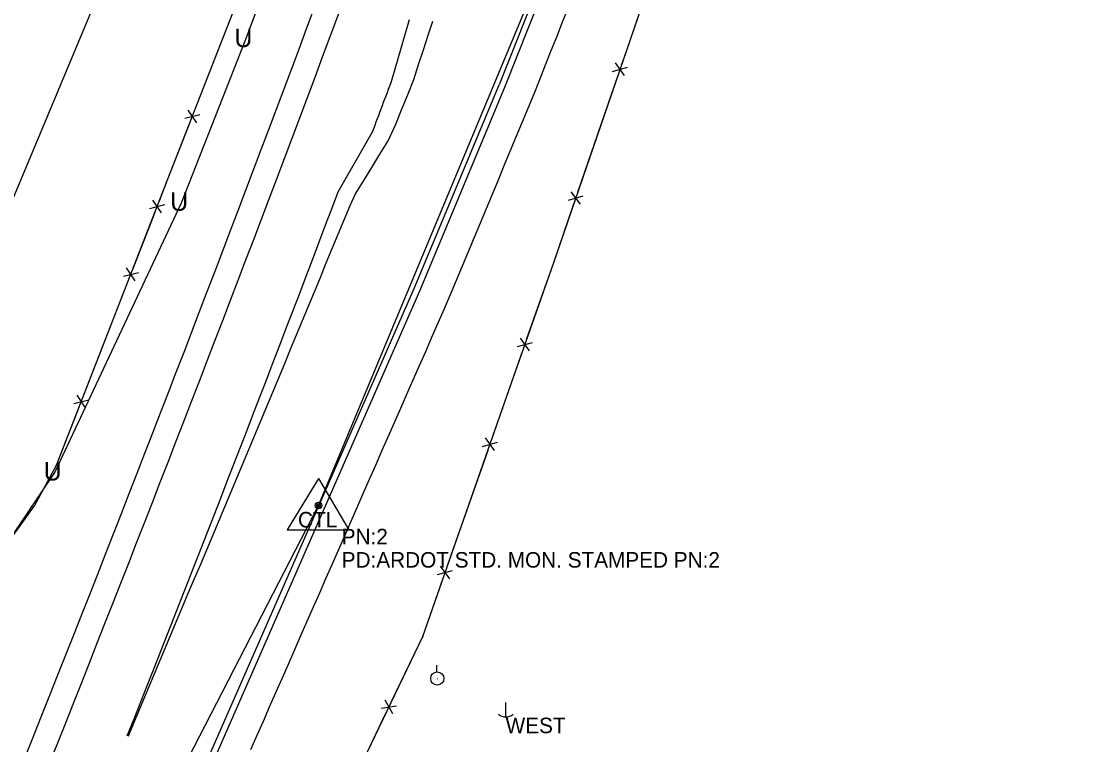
# Model space of a CAD drawing. Extents: x 1282810 to 1284464, y 402460 to 405899.
# Drawn here: x 1283065.5 to 1283408.7, y 403158.1 to 403391 of the extents above; entities that cross this region are included whole.
import ezdxf

# ---------------------------------------------------------------- set-up
doc = ezdxf.new("R2010")
doc.units = 0
for name, color, linetype in [('Default', 7, 'Continuous'), ('MOT_Proposed Road_Stage 2', 7, 'Continuous'), ('MOT_Shld_Stage 2', 7, 'Continuous'), ('MOT_Stage 1_Proposed Road', 7, 'Continuous'), ('MOT_Stage 1_Shld', 7, 'Continuous'), ('S_BASELINE', 7, 'Continuous'), ('S_DITCHLINE', 7, 'Continuous'), ('S_EDGE_PAVEMENT', 7, 'Continuous'), ('S_FENCE', 7, 'Continuous'), ('S_MSC_PT_SYM', 7, 'Continuous'), ('S_PRIMARY_CTL', 7, 'Continuous'), ('S_PRIMARY_CTL_ANNOT', 7, 'Continuous'), ('S_UNDERGROUND_CABLE', 7, 'Continuous'), ('S_UTILITY_POLE', 7, 'Continuous'), ('S_UTILITY_POLE_ANNOT', 7, 'Continuous'), ('S_UTL_PT_SYM', 7, 'Continuous'), ('S_WATER_UTILITIES', 7, 'Continuous')]:
    doc.layers.add(name, color=color, linetype=linetype)

msp = doc.modelspace()

# ---------------------------------------------------------------- linework, layer by layer
at = {"layer": 'MOT_Proposed Road_Stage 2'}
for p, q in [((1283184.98, 403372.35), (1283190.53, 403391.65)), ((1283167.56, 403336.13), (1283178.64, 403355.47))]:
    msp.add_line(p, q, dxfattribs=at)
for radius, start, end in [(11435.16, 337.333333, 339.572534), (11458.69, 339.382988, 339.473192), (11455.16, 338.332988, 339.272988)]:
    msp.add_arc((1272453.81, 407390.3), radius, start, end, dxfattribs=at)
at = {"layer": 'MOT_Shld_Stage 2'}
msp.add_arc((1272453.81, 407390.3), 11427.16, 337.333333, 339.572534, dxfattribs=at)
at = {"layer": 'MOT_Stage 1_Proposed Road'}
for p, q in [((1283408.71, 403848.09), (1283219.41, 403370.59)), ((1283192.02, 403305), (1283219.41, 403370.59)), ((1283066.46, 403019.07), (1283192.02, 403305))]:
    msp.add_line(p, q, dxfattribs=at)
at = {"layer": 'MOT_Stage 1_Shld'}
for p, q in [((1283221.27, 403369.86), (1283316.68, 403610.53)), ((1283193.86, 403304.21), (1283221.27, 403369.84)), ((1283068.3, 403018.3), (1283193.86, 403304.21))]:
    msp.add_line(p, q, dxfattribs=at)
at = {"layer": 'S_BASELINE'}
for p, q in [((1283161.19, 403235.09), (1283396.79, 403800.11)), ((1282862.35, 402655.08), (1283161.19, 403235.09))]:
    msp.add_line(p, q, dxfattribs=at)
at = {"layer": 'S_DITCHLINE'}
msp.add_lwpolyline([(1283139.44, 403156.53), (1283141.45, 403161.1), (1283143.46, 403165.68), (1283145.47, 403170.26), (1283147.48, 403174.84), (1283149.49, 403179.42), (1283151.5, 403184), (1283153.55, 403188.67), (1283155.56, 403193.25), (1283157.58, 403197.83), (1283159.59, 403202.41), (1283161.6, 403206.99), (1283163.61, 403211.57), (1283165.62, 403216.15), (1283167.63, 403220.73), (1283169.64, 403225.31), (1283171.65, 403229.89), (1283173.66, 403234.46), (1283175.63, 403238.95), (1283177.64, 403243.53), (1283179.65, 403248.1), (1283181.66, 403252.68), (1283183.67, 403257.26), (1283185.68, 403261.84), (1283187.69, 403266.42), (1283189.71, 403271), (1283191.72, 403275.58), (1283193.73, 403280.15), (1283195.74, 403284.73), (1283197.75, 403289.31), (1283199.77, 403293.92), (1283201.78, 403298.5), (1283203.75, 403303.09), (1283205.67, 403307.71), (1283207.6, 403312.32), (1283209.53, 403316.94), (1283211.45, 403321.55), (1283213.38, 403326.16), (1283215.31, 403330.78), (1283217.23, 403335.39), (1283219.15, 403339.99), (1283221.08, 403344.6), (1283223.01, 403349.21), (1283224.93, 403353.83), (1283226.86, 403358.44), (1283228.79, 403363.06), (1283230.69, 403367.68), (1283232.53, 403372.33), (1283234.37, 403376.98), (1283236.21, 403381.63), (1283238.06, 403386.28), (1283239.87, 403390.86), (1283241.72, 403395.5)], dxfattribs=at)
at = {"layer": 'S_EDGE_PAVEMENT'}
msp.add_lwpolyline([(1283099.91, 403160.8), (1283099.96, 403160.93), (1283101.91, 403165.53), (1283103.86, 403170.14), (1283105.8, 403174.75), (1283107.74, 403179.36), (1283109.67, 403183.97), (1283111.6, 403188.59), (1283113.51, 403193.21), (1283115.43, 403197.83), (1283117.37, 403202.44), (1283119.34, 403207.04), (1283121.3, 403211.64), (1283123.25, 403216.24), (1283125.21, 403220.85), (1283127.15, 403225.46), (1283129.09, 403230.07), (1283131.02, 403234.68), (1283132.95, 403239.3), (1283134.87, 403243.92), (1283136.8, 403248.54), (1283138.75, 403253.15), (1283140.69, 403257.76), (1283142.62, 403262.37), (1283144.55, 403266.99), (1283146.48, 403271.61), (1283148.39, 403276.23), (1283150.31, 403280.85), (1283152.22, 403285.47), (1283154.12, 403290.1), (1283156.03, 403294.72), (1283157.96, 403299.34), (1283159.89, 403303.96), (1283161.81, 403308.58), (1283163.73, 403313.2), (1283165.65, 403317.82), (1283167.57, 403322.44), (1283169.49, 403327.07), (1283171.4, 403331.69), (1283173.17, 403335.46), (1283175.78, 403339.73), (1283178.39, 403344), (1283181.01, 403348.26), (1283183.63, 403352.52), (1283186.07, 403357.93), (1283187.99, 403362.56), (1283189.89, 403367.19), (1283191.91, 403372.32), (1283193.45, 403377.08), (1283195.01, 403381.83), (1283196.57, 403386.59), (1283198.06, 403391.03)], dxfattribs=at)
at = {"layer": 'S_FENCE'}
for p, q in [((1283112.61, 403339.98), (1283153.51, 403444.76)), ((1283260.39, 403381.42), (1283276.92, 403429.39)), ((1283236.99, 403313.41), (1283260.39, 403381.42)), ((1283255.98, 403374.91), (1283260.78, 403376.27)), ((1283259.85, 403373.57), (1283256.91, 403377.61)), ((1283121.97, 403358.32), (1283119.2, 403362.47)), ((1283118.16, 403359.81), (1283123.01, 403360.98)), ((1283076.81, 403248.09), (1283112.61, 403339.98)), ((1283241.72, 403333.45), (1283246.52, 403334.82)), ((1283245.59, 403332.12), (1283242.65, 403336.15)), ((1283106.84, 403330.8), (1283111.7, 403331.99)), ((1283110.66, 403329.31), (1283107.88, 403333.47)), ((1283220.5, 403266.29), (1283236.99, 403313.41)), ((1283098.33, 403308.97), (1283103.19, 403310.16)), ((1283102.15, 403307.49), (1283099.38, 403311.64)), ((1283225.32, 403286.28), (1283230.13, 403287.62)), ((1283229.19, 403284.93), (1283226.27, 403288.97)), ((1283082.37, 403267.99), (1283087.22, 403269.17)), ((1283086.18, 403266.5), (1283083.41, 403270.66)), ((1283194.77, 403192.89), (1283220.5, 403266.29)), ((1283214.07, 403254.15), (1283218.88, 403255.49)), ((1283217.94, 403252.8), (1283215.02, 403256.85)), ((1283069.74, 403235), (1283076.81, 403248.09)), ((1282983.71, 403116.17), (1283069.74, 403235)), ((1283199.6, 403212.86), (1283204.41, 403214.2)), ((1283203.47, 403211.51), (1283200.54, 403215.55)), ((1283174.39, 403150.41), (1283194.77, 403192.89)), ((1283185.11, 403168.01), (1283182.65, 403172.36)), ((1283181.41, 403169.78), (1283186.34, 403170.58))]:
    msp.add_line(p, q, dxfattribs=at)
for points in [[(1283121.31, 403362.25), (1283135.8, 403399.38)], [(1283260.39, 403381.42), (1283266.88, 403400.27)], [(1283258.85, 403376.94), (1283260.39, 403381.42)], [(1283244.77, 403336.02), (1283257.73, 403373.71)], [(1283112.61, 403339.98), (1283119.86, 403358.54)], [(1283109.99, 403333.26), (1283112.61, 403339.98)], [(1283236.99, 403313.41), (1283243.47, 403332.25)], [(1283101.28, 403310.9), (1283108.54, 403329.53)], [(1283228.38, 403288.83), (1283236.99, 403313.41)], [(1283085.52, 403270.44), (1283100.04, 403307.7)], [(1283220.5, 403266.29), (1283227.07, 403285.07)], [(1283076.81, 403248.09), (1283084.07, 403266.72)], [(1283216.95, 403256.17), (1283220.5, 403266.29)], [(1283202.66, 403215.41), (1283215.82, 403252.95)], [(1283069.74, 403235), (1283076.81, 403248.09)], [(1283062.8, 403225.4), (1283069.74, 403235)], [(1283194.77, 403192.89), (1283201.35, 403211.65)], [(1283184.74, 403171.98), (1283194.77, 403192.89)], [(1283174.39, 403150.41), (1283183.02, 403168.38)]]:
    msp.add_lwpolyline(points, dxfattribs=at)
at = {"layer": 'S_MSC_PT_SYM'}
for points in [[(1283260.39, 403381.42), (1283260.39, 403381.47), (1283260.39, 403381.42), (1283260.34, 403381.42), (1283260.39, 403381.42), (1283260.39, 403381.37), (1283260.39, 403381.42), (1283260.44, 403381.42)], [(1283112.61, 403339.98), (1283112.61, 403340.03), (1283112.61, 403339.98), (1283112.56, 403339.98), (1283112.61, 403339.98), (1283112.61, 403339.93), (1283112.61, 403339.98), (1283112.66, 403339.98)], [(1283236.99, 403313.41), (1283236.99, 403313.46), (1283236.99, 403313.41), (1283236.94, 403313.41), (1283236.99, 403313.41), (1283236.99, 403313.36), (1283236.99, 403313.41), (1283237.04, 403313.41)], [(1283220.5, 403266.29), (1283220.5, 403266.34), (1283220.5, 403266.29), (1283220.45, 403266.29), (1283220.5, 403266.29), (1283220.5, 403266.24), (1283220.5, 403266.29), (1283220.55, 403266.29)], [(1283076.81, 403248.09), (1283076.81, 403248.14), (1283076.81, 403248.09), (1283076.76, 403248.09), (1283076.81, 403248.09), (1283076.81, 403248.04), (1283076.81, 403248.09), (1283076.86, 403248.09)], [(1283069.74, 403235), (1283069.74, 403235.05), (1283069.74, 403235), (1283069.69, 403235), (1283069.74, 403235), (1283069.74, 403234.95), (1283069.74, 403235), (1283069.79, 403235)], [(1283194.77, 403192.89), (1283194.77, 403192.94), (1283194.77, 403192.89), (1283194.72, 403192.89), (1283194.77, 403192.89), (1283194.77, 403192.84), (1283194.77, 403192.89), (1283194.82, 403192.89)]]:
    msp.add_lwpolyline(points, dxfattribs=at)
at = {"layer": 'S_PRIMARY_CTL'}
for p, q in [((1283161.19, 403243.79), (1283151.16, 403227.28)), ((1283161.19, 403243.79), (1283171.02, 403227.28)), ((1283151.16, 403227.28), (1283171.02, 403227.28))]:
    msp.add_line(p, q, dxfattribs=at)
for radius in [1.04, 0.609, 0.344]:
    msp.add_circle((1283161.19, 403235.09), radius, dxfattribs=at)
at = {"layer": 'S_UNDERGROUND_CABLE'}
for p, q in [((1283137.75, 403385.25), (1283157.95, 403439.2)), ((1283117.05, 403332.52), (1283137.75, 403385.25)), ((1283076.28, 403245.7), (1283117.05, 403332.52)), ((1283050.34, 403207.32), (1283076.28, 403245.7))]:
    msp.add_line(p, q, dxfattribs=at)
at = {"layer": 'S_UTILITY_POLE'}
for p, q in [((1283199.37, 403181.52), (1283199.37, 403183.63)), ((1283221.48, 403171.7), (1283221.48, 403166.98))]:
    msp.add_line(p, q, dxfattribs=at)
msp.add_circle((1283199.49, 403179.38), 2.13, dxfattribs=at)
msp.add_arc((1283221.55, 403170.4), 3.41, 226.3972, 313.6028, dxfattribs=at)
at = {"layer": 'S_UTL_PT_SYM'}
msp.add_lwpolyline([(1283199.49, 403179.38), (1283199.49, 403179.43), (1283199.49, 403179.38), (1283199.44, 403179.38), (1283199.49, 403179.38), (1283199.49, 403179.33), (1283199.49, 403179.38), (1283199.54, 403179.38)], dxfattribs=at)
at = {"layer": 'S_WATER_UTILITIES'}
msp.add_line((1283061.96, 403331.96), (1283091.5, 403402.51), dxfattribs=at)

# ---------------------------------------------------------------- texts
at = {"layer": 'Default'}
for p in [(1283134.12, 403382.71), (1283113.43, 403329.98), (1283072.66, 403243.16)]:
    msp.add_text('U', height=6, rotation=360, dxfattribs=at).set_placement(p)
at = {"layer": 'S_PRIMARY_CTL'}
msp.add_text('CTL', height=5, rotation=360, dxfattribs=at).set_placement((1283154.6, 403228.02))
at = {"layer": 'S_PRIMARY_CTL_ANNOT'}
for s, p in [('PN:2', (1283168.69, 403222.59)), ('PD:ARDOT STD. MON. STAMPED PN:2', (1283168.69, 403215.09))]:
    msp.add_text(s, height=5, dxfattribs=at).set_placement(p)
at = {"layer": 'S_UTILITY_POLE_ANNOT'}
msp.add_text('WEST', height=5, dxfattribs=at).set_placement((1283221.5, 403161.76))

doc.saveas('drawing.dxf')
